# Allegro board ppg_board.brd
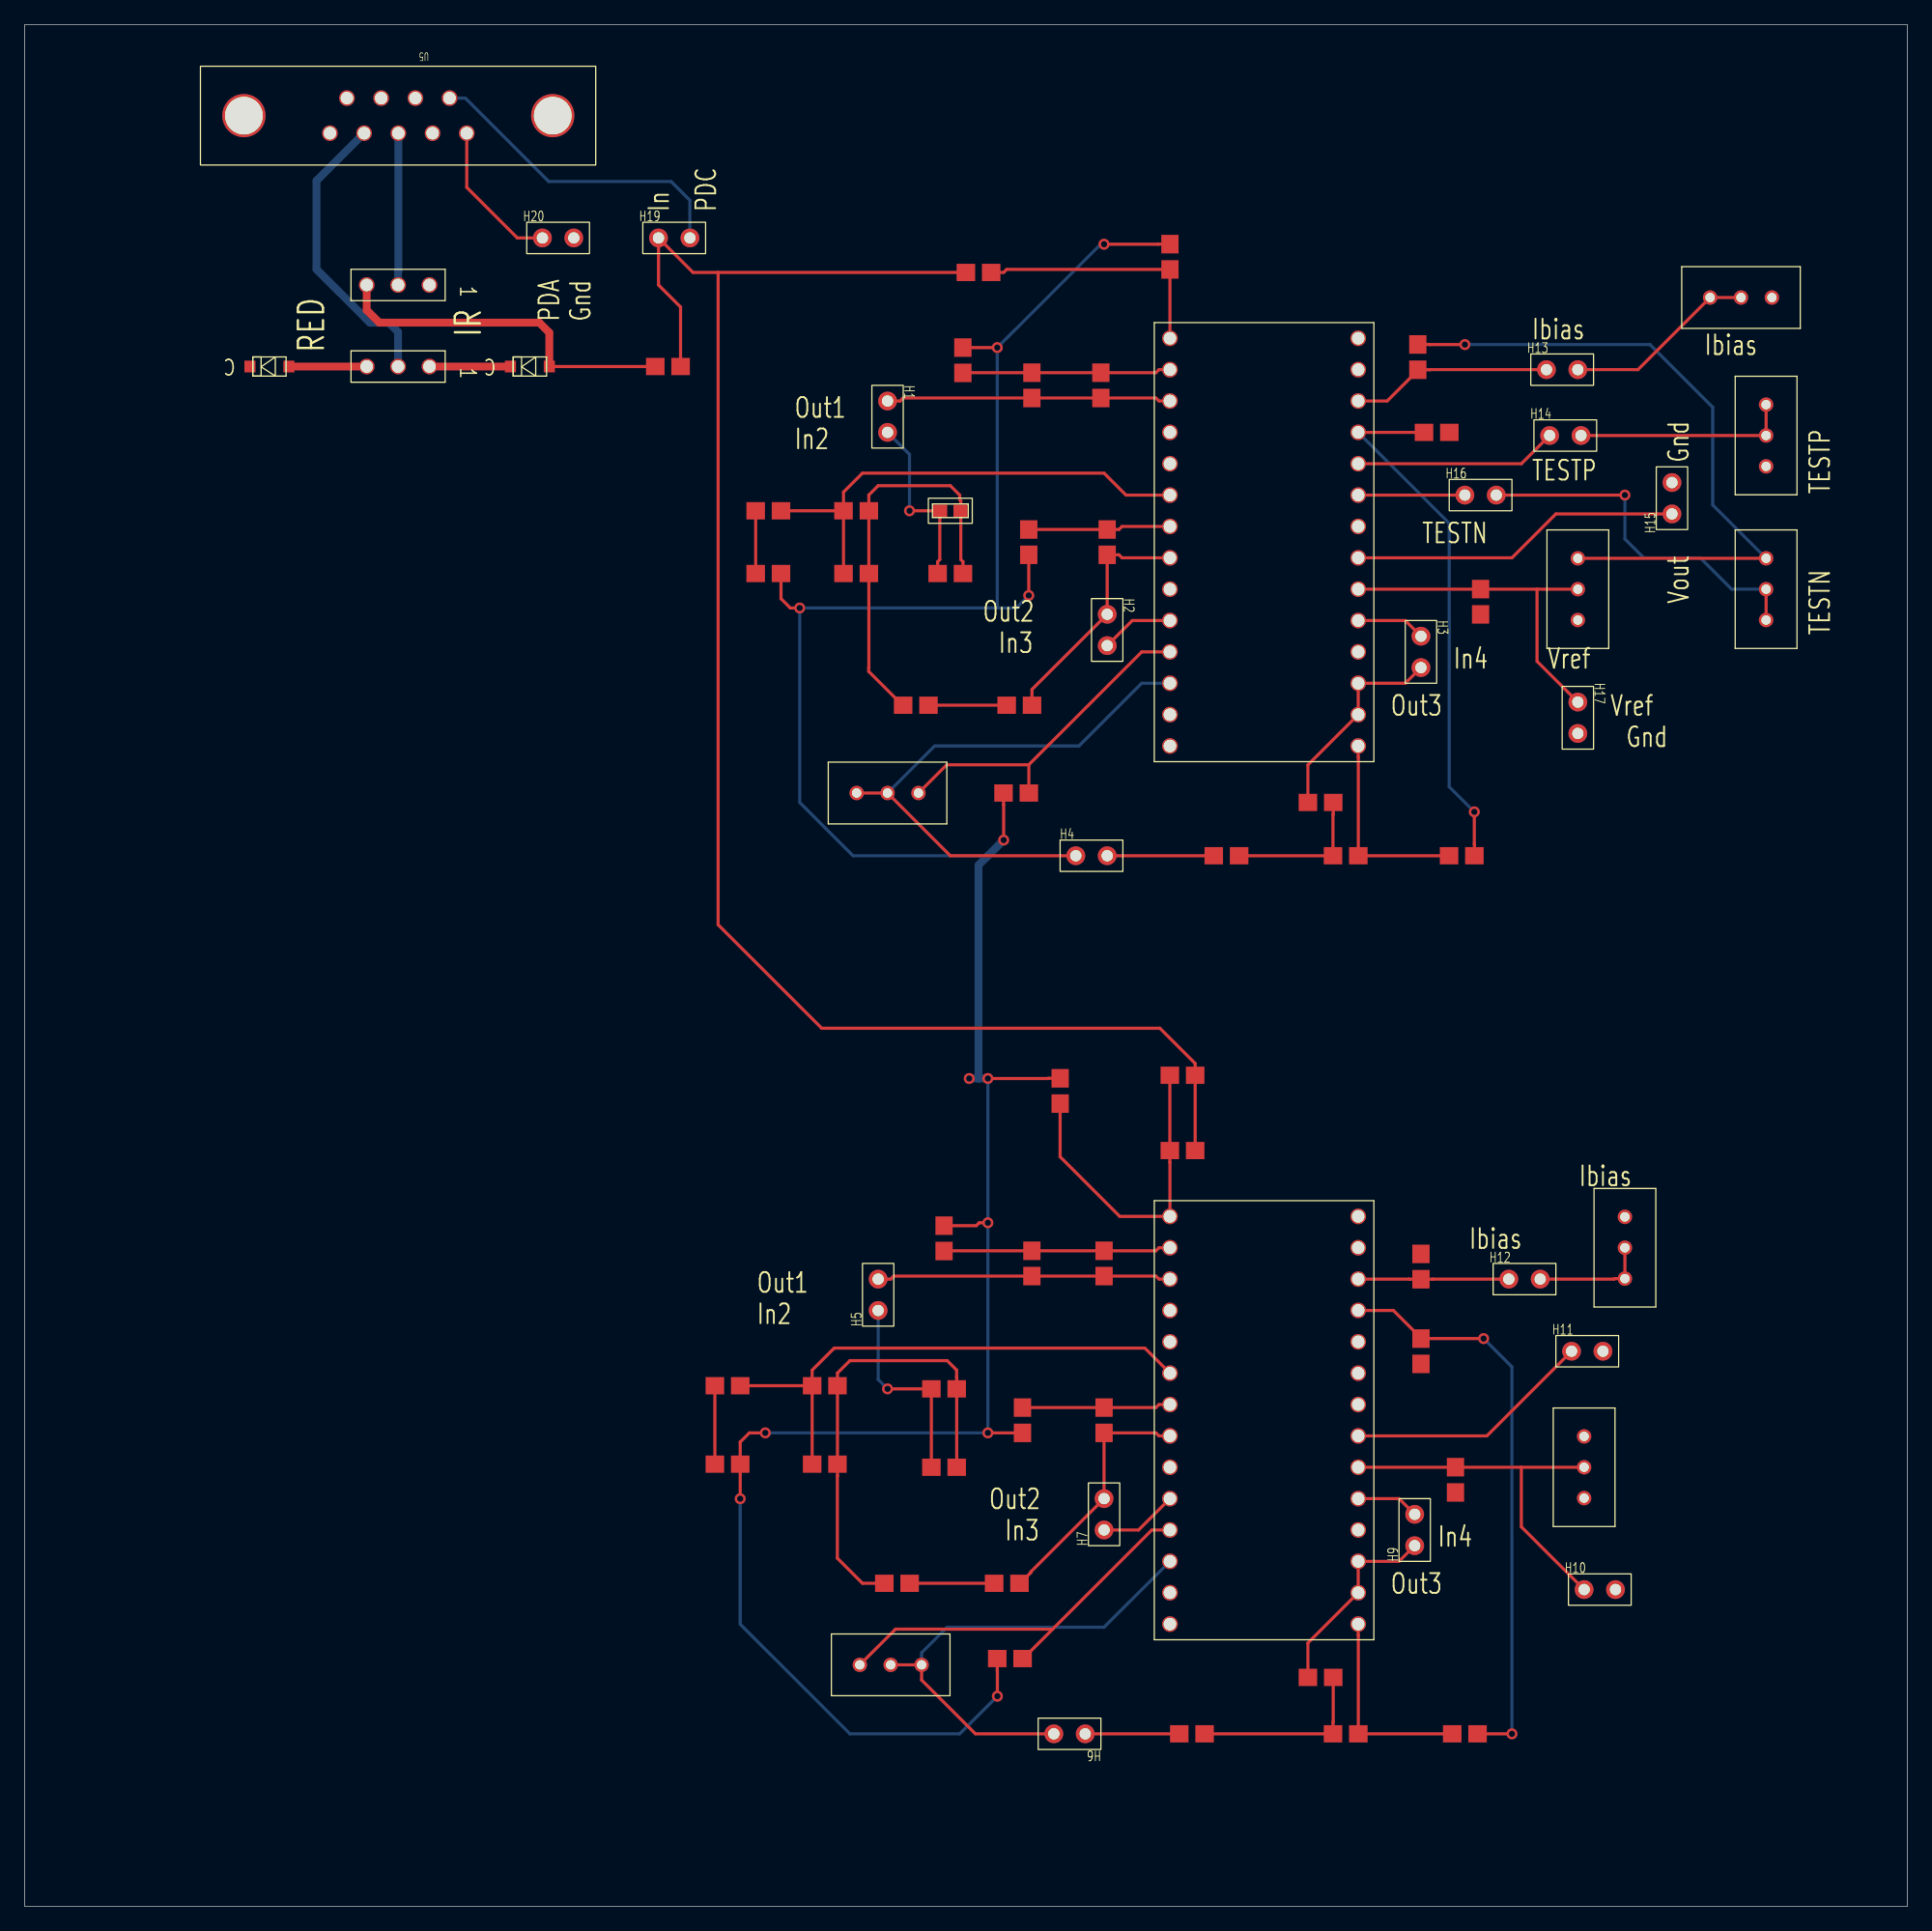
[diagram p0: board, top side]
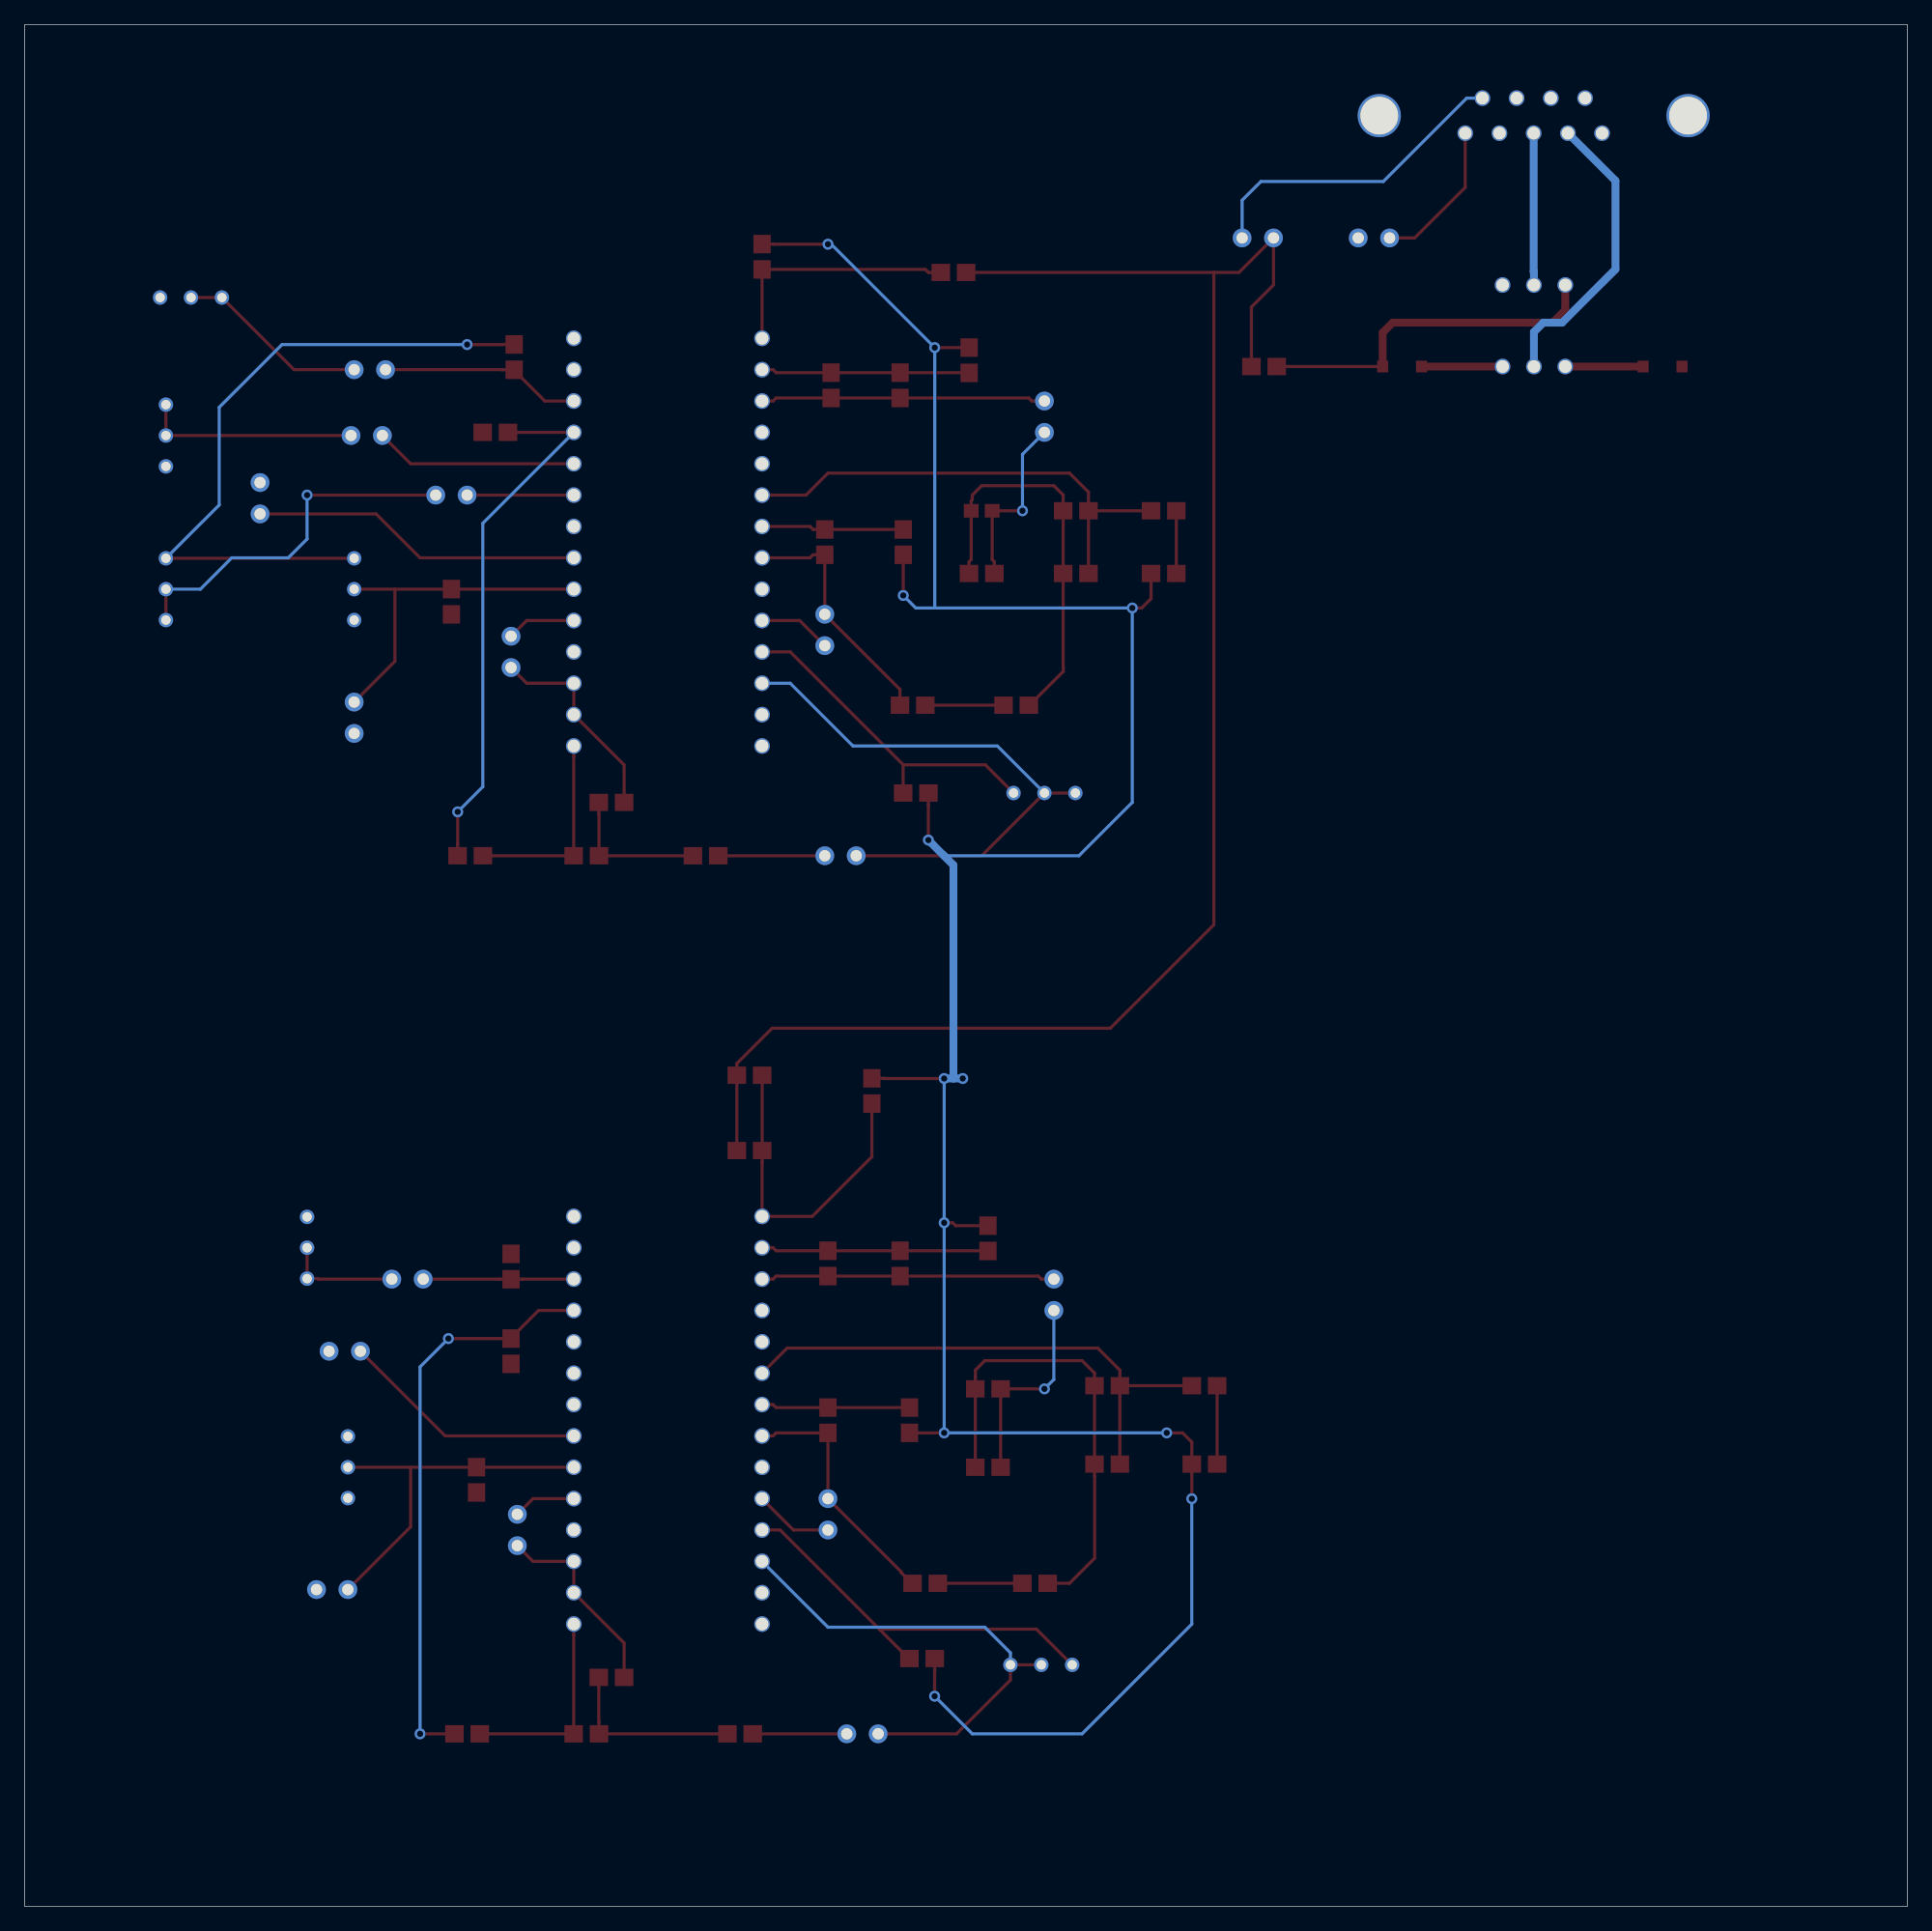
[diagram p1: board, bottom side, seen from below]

Outline 152.4 x 152.4 mm; copper layers: TOP, BOTTOM. Coordinates in mm from the lower left corner of the outline.
Outline path: 0,152.4 0,0 152.4,0 152.4,152.4 0,152.4

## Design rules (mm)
net group PB: nets PB<0> PB<1> PB<2> PB<3> PB<4> PB<5>
net group PD: nets PD<0> PD<1> PD<2> PD<3> PD<4> PD<5> PD<6> PD<7>

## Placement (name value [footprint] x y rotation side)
C1  -  [GR_0805]  77.22 132.33 0 top
C2  -  [GR_0805]  87.12 123.19 270 top
C3  -  [GR_0603]  74.93 113.03 0 top
C4  -  [GR_0805]  74.93 107.95 0 top
C5  -  [GR_0805]  67.31 113.03 180 top
C6  -  [GR_0805]  67.31 107.95 180 top
C7  -  [GR_0805]  93.73 61.21 0 top
C8  -  [GR_0805]  93.73 67.31 0 top
C9  -  [GR_0805]  87.38 52.07 90 top
C10  -  [GR_0805]  74.42 41.91 180 top
C11  -  [GR_0805]  74.42 35.56 180 top
C12  -  [GR_0805]  64.77 42.16 0 top
C13  -  [GR_0805]  64.77 35.81 0 top
C14  -  [GR_0805]  116.59 13.97 180 top
C15  -  [GR_0805]  115.82 34.54 90 top
C16  -  [GR_0805]  113.03 44.96 90 top
C17  -  [GR_0805]  113.03 51.82 270 top
C18  -  [GR_0805]  112.78 125.48 270 top
C19  -  [GR_0805]  114.3 119.38 180 top
C20  -  [GR_0805]  104.9 18.54 180 top
C21  -  [GR_0805]  116.33 85.09 180 top
C22  -  [GR_0805]  104.9 89.41 0 top
C23  -  [GR_0805]  117.86 105.66 90 top
H1  -  [JUMPER2]  69.85 121.92 270 top
H2  -  [JUMPER2]  87.63 104.65 270 top
H3  -  [JUMPER2]  113.03 102.87 270 top
H4  -  [JUMPER2]  85.09 85.09 0 top
H5  -  [JUMPER2]  69.09 48.26 90 top
H6  -  [JUMPER2]  85.85 13.97 180 top
H7  -  [JUMPER2]  87.38 30.48 90 top
H8  -  [GR_HEADER_SIP3]  30.23 131.32 270 top
H9  -  [JUMPER2]  112.52 29.21 90 top
H10  -  [JUMPER2]  126.24 25.65 0 top
H11  -  [JUMPER2]  125.22 44.96 0 top
H12  -  [JUMPER2]  120.14 50.8 0 top
H13  -  [JUMPER2]  123.19 124.46 0 top
H14  -  [JUMPER2]  123.44 119.13 0 top
H15  -  [JUMPER2]  133.35 112.78 90 top
H16  -  [JUMPER2]  116.59 114.3 0 top
H17  -  [JUMPER2]  125.73 97.54 270 top
H18  -  [GR_HEADER_SIP3]  30.23 124.71 270 top
H19  -  [JUMPER2]  51.31 135.13 0 top
H20  -  [JUMPER2]  41.91 135.13 0 top
R2  -  [GR_0805]  87.38 39.37 90 top
R3  -  [GR_0805]  79.5 26.16 180 top
R4  -  [GR_0805]  80.77 39.37 270 top
R5  -  [MURATAPV36W]  138.94 130.3 90 top
R6  -  [MURATAPV36W]  126.24 35.56 0 top
R7  -  [MURATAPV36W]  140.97 119.13 0 top
R8  -  [MURATAPV36W]  129.54 53.34 180 top
R9  -  [GR_0805]  56.9 35.81 0 top
R10  -  [GR_0805]  56.9 42.16 180 top
R11  -  [GR_0805]  70.61 26.16 180 top
R12  -  [MURATAPV36W]  140.97 106.68 180 top
R13  -  [GR_0805]  81.53 52.07 90 top
R14  -  [GR_0805]  52.07 124.71 180 top
R15  -  [GR_0805]  74.42 54.1 90 top
R16  -  [GR_0805]  83.82 66.04 90 top
R17  -  [MURATAPV36W]  125.73 106.68 0 top
R18  -  [GR_0805]  94.49 13.97 0 top
R19  -  [MURATAPV36W]  69.85 90.17 270 top
R20  -  [GR_0805]  106.93 13.97 0 top
R21  -  [MURATAPV36W]  70.1 19.56 270 top
R22  -  [GR_0805]  92.71 133.6 90 top
R23  -  [GR_0805]  75.95 125.22 90 top
R24  -  [GR_0805]  81.53 123.19 270 top
R25  -  [GR_0805]  72.14 97.28 0 top
R26  -  [GR_0805]  60.2 107.95 0 top
R27  -  [GR_0805]  60.2 113.03 180 top
R28  -  [GR_0805]  81.28 110.49 270 top
R29  -  [GR_0805]  80.52 97.28 0 top
R30  -  [GR_0805]  87.63 110.49 270 top
R31  -  [GR_0805]  79.76 20.07 180 top
R32  -  [GR_0805]  80.26 90.17 180 top
R33  -  [GR_0805]  106.93 85.09 180 top
R34  -  [GR_0805]  97.28 85.09 180 top
U1  -  [DIP28_SOCKET]  100.33 110.49 0 top
U2  -  [DIP28_SOCKET]  100.33 39.37 0 top
U3  -  [GR_SOD123]  19.81 124.71 180 top
U4  -  [GR_SOD123]  40.89 124.71 180 top
U5  -  [GR_DB9_AE10924-ND]  30.23 145.03 180 top

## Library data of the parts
C1 = GR_CAP: part number: GR_CAP-1.2UF,GR_0805,10%
C2 C13 = GR_CAP: part number: GR_CAP-150NF,GR_0805,10%
C3 = GR_CAP: part number: GR_CAP-15UF,GR_0603,20%
C4 = GR_CAP: part number: GR_CAP-1UF,GR_0805,10%
C5 = GR_CAP: part number: GR_CAP-4.7UF,GR_0805,10%
C6 C10 = GR_CAP: part number: GR_CAP-1.5UF,GR_0805,10%
C7 = GR_CAP: part number: GR_CAP-120NF,GR_0805,5%
C8 C12 = GR_CAP: part number: GR_CAP-470NF,GR_0805,10%
C9 C11 C14 C20-C22 = GR_CAP: part number: GR_CAP-100NF,GR_0805,10%
C15-C19 C23 = GR_CAP: part number: GR_CAP-10NF,GR_0805,10%
H1-H7 H9-H17 H19 H20 = HEADER_SIP2: part number: HEADER_SIP2-SIP HEADER
H8 H18 = GR_HEADER_SIP3
R2 R30 = GR_RES: part number: GR_RES-40.2K,1%,GR_0805
R3 R10 = GR_RES: part number: GR_RES-619K,1%,GR_0805
R4 R28 R32 = GR_RES: part number: GR_RES-10K,1%,GR_0805
R5 R7 R8 R12 = POT: part number: POT-500K,MURATAPV36W
R6 R17 = POT: part number: POT-200K,MURATAPV36W
R9 R26 = GR_RES: part number: GR_RES-0,JUMPER,GR_0805
R11 = GR_RES: part number: GR_RES-976K,1%,GR_0805
R13 R16 = GR_RES: part number: GR_RES-499K,1%,GR_0805
R14 R15 = GR_RES: part number: GR_RES-100K,1%,GR_0805
R18 R20 = GR_RES: part number: GR_RES-110K,1%,GR_0805
R19 R21 = POT: part number: POT-100K,MURATAPV36W
R22 = GR_RES: part number: GR_RES-3.01M,1%,GR_0805
R23 R33 R34 = GR_RES: part number: GR_RES-1.00M,1%,GR_0805
R24 = GR_RES: part number: GR_RES-4.99M,1%,GR_0805
R25 = GR_RES: part number: GR_RES-9.76M,1%,GR_0805
R27 R29 = GR_RES: part number: GR_RES-6.19M,1%,GR_0805
R31 = GR_RES: part number: GR_RES-49.9K,1%,GR_0805
U1 U2 = DIP28_SOCKET
U3 U4 = GR_AL5809
U5 = GR_NELLCOR_DB9

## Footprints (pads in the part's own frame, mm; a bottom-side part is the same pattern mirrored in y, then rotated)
DIP28_SOCKET
  round 1.27 hole 1.016: 1(-7.62,16.51) 2(-7.62,13.97) 3(-7.62,11.43) 4(-7.62,8.89) 5(-7.62,6.35) 6(-7.62,3.81) 7(-7.62,1.27) 8(-7.62,-1.27) 9(-7.62,-3.81) 10(-7.62,-6.35) 11(-7.62,-8.89) 12(-7.62,-11.43) 13(-7.62,-13.97) 14(-7.62,-16.51) 15(7.62,-16.51) 16(7.62,-13.97) 17(7.62,-11.43) 18(7.62,-8.89) 19(7.62,-6.35) 20(7.62,-3.81) 21(7.62,-1.27) 22(7.62,1.27) 23(7.62,3.81) 24(7.62,6.35) 25(7.62,8.89) 26(7.62,11.43) 27(7.62,13.97) 28(7.62,16.51)
GR_0603
  rect 1.2x1.1 smd: 1(-0.85,0) 2(0.85,0)
GR_0805
  rect 1.5x1.4 smd: 1(-1.025,0) 2(1.025,0)
GR_DB9_AE10924-ND
  round 3.5 hole 3.05: (-12.52,0) (12.48,0)
  round 1.27 hole 1.016: 1(5.52,1.42) 2(2.75,1.42) 3(-0.02,1.42) 4(-2.79,1.42) 5(-5.56,1.42) 6(4.14,-1.42) 7(1.37,-1.42) 8(-1.4,-1.42) 9(-4.17,-1.42)
GR_HEADER_SIP3
  round 1.27 hole 1.016: 1(0,2.54) 2(0,0) 3(0,-2.54)
GR_SOD123
  rect 0.9x0.95 smd: 1(-1.575,0) 2(1.575,0)
JUMPER2
  round 1.524 hole 0.914: 1(0,0) 2(2.54,0)
MURATAPV36W
  round 1.168 hole 0.762: 1(0,2.5) 2(0,0) 3(0,-2.5)

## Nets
GND: C15.1 C16.1 C19.1 C23.1 H8.1 H10.2 H11.2 H15.2 H17.2 H20.2 R5.3 R6.3 R7.3 R8.3 R17.3 U1.13 U1.14 U2.13 U2.14 U3.2(CATHODE)
VDD_5: H8.3 R14.2 U4.1(ANODE)
VDD_18: C17.1 C18.1 R6.1 R12.3 R17.1
VDDA: U1.27 U1.28 U2.27 U2.28
UNNAMED_1_DIP28SOCKET_I8_IBIAS: C18.2 H13.1 U1.26(IBIAS)
UNNAMED_1_DIP28SOCKET_I8_OUT2: H2.1 R29.2 R30.2 U1.8(OUT2)
UNNAMED_1_DIP28SOCKET_I8_OUT3: H4.1 R19.2 R19.3 U1.12(OUT3)
UNNAMED_1_DIP28SOCKET_I8_TESTN: H16.1 U1.23(TESTN)
UNNAMED_1_DIP28SOCKET_I8_TESTP: H14.1 U1.24(TESTP)
UNNAMED_1_DIP28SOCKET_I8_VIN1: C1.2 R22.1 U1.1(VIN1+)
UNNAMED_1_DIP28SOCKET_I8_VIN1_1: C2.1 R23.1 R24.1 U1.2(VIN1-)
UNNAMED_1_DIP28SOCKET_I8_VIN2: R28.1 R30.1 U1.7(VIN2-)
UNNAMED_1_DIP28SOCKET_I8_VIN2_1: C5.2 C6.2 R27.1 U1.6(VIN2+)
UNNAMED_1_DIP28SOCKET_I8_VIN3: R19.1 R32.1 U1.11(VIN3-)
UNNAMED_1_DIP28SOCKET_I8_VIN3_1: H2.2 U1.10(VIN3+)
UNNAMED_1_DIP28SOCKET_I8_VIN4: C21.2 R33.1 U1.15(VIN4+)
UNNAMED_1_DIP28SOCKET_I8_VIN4_1: C22.1 H3.2 U1.16(VIN4-) U1.17(VOUT4)
UNNAMED_1_DIP28SOCKET_I8_VINCOM: H3.1 U1.19(VIN_COMP)
UNNAMED_1_DIP28SOCKET_I8_VOUT1: C2.2 H1.1 R24.2 U1.3(VOUT1)
UNNAMED_1_DIP28SOCKET_I8_VOUTCO: H15.1 U1.21(VOUT_COMP)
UNNAMED_1_DIP28SOCKET_I8_VREFCO: C23.2 H17.1 R17.2 U1.20(VREF_COMP)
UNNAMED_1_DIP28SOCKET_I53_IBIAS: C17.2 H12.1 U2.26(IBIAS)
UNNAMED_1_DIP28SOCKET_I53_OUT2: H7.2 R2.1 R3.1 U2.8(OUT2)
UNNAMED_1_DIP28SOCKET_I53_OUT3: H6.2 R21.1 R21.2 U2.12(OUT3)
UNNAMED_1_DIP28SOCKET_I53_VIN1: C7.1 C8.1 R16.1 U2.1(VIN1+)
UNNAMED_1_DIP28SOCKET_I53_VIN1_: C9.2 R13.2 R15.1 U2.2(VIN1-)
UNNAMED_1_DIP28SOCKET_I53_VIN2: C12.1 C13.1 R10.1 U2.6(VIN2+)
UNNAMED_1_DIP28SOCKET_I53_VIN2_: R2.2 R4.1 U2.7(VIN2-)
UNNAMED_1_DIP28SOCKET_I53_VIN3: H7.1 U2.10(VIN3+)
UNNAMED_1_DIP28SOCKET_I53_VIN3_: R21.3 R31.1 U2.11(VIN3-)
UNNAMED_1_DIP28SOCKET_I53_VIN4: C20.2 H9.1 U2.16(VIN4-) U2.17(VOUT4)
UNNAMED_1_DIP28SOCKET_I53_VIN4_: C14.2 R20.2 U2.15(VIN4+)
UNNAMED_1_DIP28SOCKET_I53_VINCO: H9.2 U2.19(VIN_COMP)
UNNAMED_1_DIP28SOCKET_I53_VOUT1: C9.1 H5.2 R13.1 U2.3(VOUT1)
UNNAMED_1_DIP28SOCKET_I53_VOUTC: H11.1 U2.21(VOUT_COMP)
UNNAMED_1_DIP28SOCKET_I53_VREFC: C15.2 H10.1 R6.2 U2.20(VREF_COMP)
UNNAMED_1_GRAL5809_I76_CATHODE: H18.1 U4.2(CATHODE)
UNNAMED_1_GRAL5809_I77_ANODE: H18.3 U3.1(ANODE)
UNNAMED_1_GRCAP_IC3RR_1: C3.1 C4.1 H1.2
UNNAMED_1_GRCAP_IC3RR_2: C3.2 C4.2 C5.1 C6.1 R25.1
UNNAMED_1_GRCAP_IC4HR_1: C10.1 C11.1 C12.2 C13.2 R11.2
UNNAMED_1_GRCAP_IC4HR_2: C10.2 C11.2 H5.1
UNNAMED_1_GRCAP_IC7RR_2: C22.2 R33.2 R34.1
UNNAMED_1_GRCAP_IC9HR_1: C20.1 R18.2 R20.1
UNNAMED_1_GRHEADERSIP3_I74_2: H8.2 U5.3(IR_CATHODE)
UNNAMED_1_GRHEADERSIP3_I75_2: H18.2 U5.2(IR_ANODE)
UNNAMED_1_GRNELLCORDB9_I71_PDAN: H20.1 U5.5(PD_ANODE)
UNNAMED_1_GRNELLCORDB9_I71_PDCA: H19.2 U5.9(PD_CATHODE)
UNNAMED_1_GRRES_IR4HR_2: R9.1 R10.2
UNNAMED_1_GRRES_IR4RR_2: R26.1 R27.2
UNNAMED_1_GRRES_IR6RR_2: R25.2 R29.1
UNNAMED_1_GRRES_IR7HR_2: R3.2 R11.1
UNNAMED_1_GRRES_IR12HR_1: H6.1 R18.1
UNNAMED_1_HEADERSIP2_I40_2: H4.2 R34.2
UNNAMED_1_HEADERSIP2_I66_2: H12.2 R8.1 R8.2
UNNAMED_1_POT_I4_2: H13.2 R5.1 R5.2
UNNAMED_1_POT_I45_1: H16.2 R12.1 R12.2
UNNAMED_1_POT_I46_1: H14.2 R7.1 R7.2
VCM: C14.1 C16.2 C19.2 C21.1 R4.2 R9.2 R15.2 R16.2 R22.2 R23.2 R26.2 R28.2 R31.2 R32.2 U1.25(VCMA) U2.25(VCMA)
VOUT_PD: C1.1 C7.2 C8.2 H19.1 R14.1

Pads without a net: U1 4 5 9 18 22; U2 4 5 9 18 22 23 24; U5 1 4 6 7 8

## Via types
v1: diameter 0.889, hole 0.508, TOP to BOTTOM, 19 vias

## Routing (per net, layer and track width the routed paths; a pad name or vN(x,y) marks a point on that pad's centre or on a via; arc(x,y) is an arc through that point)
VDD_5: length 28.9
  TOP w0.254: U4.1 R14.2
  TOP w0.635: U4.1 42.47,127.46 41.66,128.27 28.7,128.27 27.69,129.29 H8.3
VDD_18: length 55.2
  TOP w0.254: R17.1 R12.3 ; C18.1 113.73,126.5 113.74,126.49 v1(116.59,126.49)
  BOTTOM w0.254: v1(116.59,126.49) 131.57,126.49 136.65,121.41 136.65,113.5 R12.3
UNNAMED_1_DIP28SOCKET_I8_IBIAS: length 16.3
  TOP w0.254: U1.26 110.29,121.92 112.78,124.4 C18.2 113.73,124.45 113.74,124.46 H13.1
UNNAMED_1_DIP28SOCKET_I8_OUT2: length 19.9
  TOP w0.254: R29.2 81.54,98.56 H2.1 R30.2 88.58,109.47 88.83,109.22 U1.8
UNNAMED_1_DIP28SOCKET_I8_OUT3: length 46.4
  TOP w0.254: R19.3 R19.2 74.93,85.09 H4.1
  BOTTOM w0.254: R19.2 73.66,93.98 85.34,93.98 90.42,99.06 U1.12
UNNAMED_1_DIP28SOCKET_I8_TESTN: length 8.6
  TOP w0.254: H16.1 U1.23
UNNAMED_1_DIP28SOCKET_I8_TESTP: length 16.4
  TOP w0.254: H14.1 121.16,116.84 U1.24
UNNAMED_1_DIP28SOCKET_I8_VIN1: length 20.1
  TOP w0.254: U1.1 R22.1 79.49,132.58 79.24,132.33 C1.2
UNNAMED_1_DIP28SOCKET_I8_VIN1_1: length 16.9
  TOP w0.254: 75.95,124.21 R24.1 C2.1 91.58,124.21 91.82,124.46 U1.2
UNNAMED_1_DIP28SOCKET_I8_VIN2: length 11.5
  TOP w0.254: R28.1 R30.1 88.58,111.51 88.83,111.76 U1.7
UNNAMED_1_DIP28SOCKET_I8_VIN2_1: length 39.5
  TOP w0.254: R27.1 C5.2 ; C5.2 C6.2 ; C5.2 66.29,114.55 67.82,116.08 87.38,116.08 89.15,114.3 U1.6
UNNAMED_1_DIP28SOCKET_I8_VIN3: length 27.4
  TOP w0.254: R19.1 74.64,92.46 81.28,92.46 ; U1.11 90.42,101.6 81.29,92.46 R32.1
UNNAMED_1_DIP28SOCKET_I8_VIN3_1: length 5.9
  TOP w0.254: H2.2 89.66,104.14 U1.10
UNNAMED_1_DIP28SOCKET_I8_VIN4: length 16.2
  TOP w0.254: U1.15 107.95,93.09 107.96,93.08 R33.1 C21.2
UNNAMED_1_DIP28SOCKET_I8_VIN4_1: length 16.9
  TOP w0.254: C22.1 103.88,92.45 U1.16 U1.17 111.76,99.06 H3.2
UNNAMED_1_DIP28SOCKET_I8_VINCOM: length 5.6
  TOP w0.254: U1.19 111.76,104.14 H3.1
UNNAMED_1_DIP28SOCKET_I8_VOUT1: length 23.1
  TOP w0.254: H1.1 70.87,121.92 71.11,122.17 R24.2 C2.2 91.58,122.17 91.82,121.92 U1.3
UNNAMED_1_DIP28SOCKET_I8_VOUTCO: length 26.9
  TOP w0.254: U1.21 120.4,109.22 123.95,112.78 H15.1
UNNAMED_1_DIP28SOCKET_I8_VREFCO: length 28.3
  TOP w0.254: U1.20 122.43,106.68 ; 122.43,106.68 122.43,100.84 H17.1 ; 122.43,106.68 R17.2
UNNAMED_1_DIP28SOCKET_I53_IBIAS: length 12.2
  TOP w0.254: H12.1 113.99,50.8 113.98,50.79 C17.2 112.08,50.79 112.07,50.8 U2.26
UNNAMED_1_DIP28SOCKET_I53_OUT2: length 20.5
  TOP w0.254: U2.8 91.82,38.1 91.58,38.35 R2.1 H7.2 81.46,27.1 81.46,27.04 80.58,26.16 R3.1
UNNAMED_1_DIP28SOCKET_I53_OUT3: length 40.4
  TOP w0.254: H6.2 76.96,13.97 72.6,18.33 R21.1 R21.2
  BOTTOM w0.254: U2.12 87.38,22.61 74.68,22.61 72.6,20.53 R21.1
UNNAMED_1_DIP28SOCKET_I53_VIN1: length 26.6
  TOP w0.254: R16.1 83.82,60.71 88.65,55.88 U2.1 92.71,60.25 92.7,60.26 C7.1 C8.1
UNNAMED_1_DIP28SOCKET_I53_VIN1_: length 17.9
  TOP w0.254: 74.93,53.09 R13.2 C9.2 91.58,53.09 91.82,53.34 U2.2
UNNAMED_1_DIP28SOCKET_I53_VIN2: length 44
  TOP w0.254: R10.1 C12.1 ; C12.1 63.75,43.43 65.53,45.21 90.68,45.21 U2.6 ; C12.1 C13.1
UNNAMED_1_DIP28SOCKET_I53_VIN2_: length 12
  TOP w0.254: R4.1 R2.2 91.58,40.39 91.82,40.64 U2.7
UNNAMED_1_DIP28SOCKET_I53_VIN3: length 6.4
  TOP w0.254: U2.10 90.17,30.48 H7.1
UNNAMED_1_DIP28SOCKET_I53_VIN3_: length 33.1
  TOP w0.254: R21.3 70.5,22.45 83.21,22.45 ; U2.11 91.24,30.48 83.21,22.45 ; 83.21,22.45 80.83,20.07 R31.1
UNNAMED_1_DIP28SOCKET_I53_VIN4: length 16.2
  TOP w0.254: C20.2 103.88,21.33 U2.16 U2.17 111.25,27.94 H9.1
UNNAMED_1_DIP28SOCKET_I53_VIN4_: length 16.5
  TOP w0.254: U2.15 107.95,21.97 107.96,21.96 R20.2 C14.2
UNNAMED_1_DIP28SOCKET_I53_VINCO: length 5.1
  TOP w0.254: H9.2 111.25,33.02 U2.19
UNNAMED_1_DIP28SOCKET_I53_VOUT1: length 23.8
  TOP w0.254: U2.3 91.82,50.8 91.58,51.05 C9.1 R13.1 70.35,51.05 70.1,50.8 H5.2
UNNAMED_1_DIP28SOCKET_I53_VOUTC: length 20.1
  TOP w0.254: H11.1 118.36,38.1 U2.21
UNNAMED_1_DIP28SOCKET_I53_VREFC: length 30.3
  TOP w0.254: 121.16,35.56 R6.2 ; 121.16,35.56 121.16,30.73 H10.1 ; 121.16,35.56 U2.20
UNNAMED_1_GRAL5809_I76_CATHODE: length 6.6
  TOP w0.635: U4.2 H18.1
UNNAMED_1_GRAL5809_I77_ANODE: length 6.3
  TOP w0.635: U3.1 H18.3
UNNAMED_1_GRCAP_IC3RR_1: length 14.7
  TOP w0.254: v1(71.63,113.03) C3.1 74.08,109.08 73.91,108.9 C4.1
  BOTTOM w0.254: H1.2 71.63,117.6 v1(71.63,113.03)
UNNAMED_1_GRCAP_IC3RR_2: length 32.7
  TOP w0.254: R25.1 71.06,97.28 68.33,100.02 68.33,100.33 68.33,100.34 C6.1 C5.1 68.33,114.31 69.09,115.06 74.93,115.06 75.69,114.3 75.69,113.92 75.78,113.83 C3.2 75.78,109.08 75.95,108.9 C4.2
UNNAMED_1_GRCAP_IC4HR_1: length 37.9
  TOP w0.254: R11.2 67.82,26.16 65.79,28.19 65.79,34.85 65.79,34.86 C13.2 C12.2 65.79,43.19 66.8,44.2 74.68,44.2 75.44,43.43 75.44,42.87 75.45,42.86 C10.1 C11.1
UNNAMED_1_GRCAP_IC4HR_2: length 16.6
  TOP w0.254: C11.2 C10.2 v1(69.85,41.91)
  BOTTOM w0.254: H5.1 69.09,42.67 v1(69.85,41.91)
UNNAMED_1_GRCAP_IC7RR_2: length 11.9
  TOP w0.254: C22.2 105.93,88.45 105.91,88.44 R33.2 R34.1
UNNAMED_1_GRCAP_IC9HR_1: length 15
  TOP w0.254: C20.1 105.93,14.94 105.91,14.92 R20.1 R18.2
UNNAMED_1_GRHEADERSIP3_I74_2: length 12.3
  BOTTOM w0.635: H8.2 30.23,132.4 30.25,132.42 U5.3
UNNAMED_1_GRHEADERSIP3_I75_2: length 24.1
  BOTTOM w0.635: U5.2 23.62,139.76 23.62,132.59 27.94,128.27 29.46,128.27 30.23,127.51 H18.2
UNNAMED_1_GRNELLCORDB9_I71_PDAN: length 12.2
  TOP w0.254: H20.1 39.88,135.13 35.79,139.22 U5.5
UNNAMED_1_GRNELLCORDB9_I71_PDCA: length 25.9
  BOTTOM w0.254: U5.9 35.66,146.45 42.42,139.7 52.32,139.7 53.85,138.18 H19.2
UNNAMED_1_GRRES_IR4HR_2: length 6.3
  TOP w0.254: R9.1 R10.2
UNNAMED_1_GRRES_IR4RR_2: length 5.1
  TOP w0.254: R27.2 R26.1
UNNAMED_1_GRRES_IR6RR_2: length 6.3
  TOP w0.254: R29.1 R25.2
UNNAMED_1_GRRES_IR7HR_2: length 6.8
  TOP w0.254: R3.2 R11.1
UNNAMED_1_GRRES_IR12HR_1: length 7.6
  TOP w0.254: R18.1 H6.1
UNNAMED_1_HEADERSIP2_I40_2: length 8.6
  TOP w0.254: H4.2 R34.2
UNNAMED_1_HEADERSIP2_I66_2: length 9.4
  TOP w0.254: H12.2 128.66,50.8 128.7,50.84 R8.1 R8.2
UNNAMED_1_POT_I4_2: length 15.6
  TOP w0.254: R5.2 R5.1 130.6,124.46 H13.2
UNNAMED_1_POT_I45_1: length 29.6
  TOP w0.254: R12.1 R12.2 ; H16.2 v1(129.54,114.3)
  BOTTOM w0.254: v1(129.54,114.3) 129.54,110.74 131.06,109.22 135.64,109.22 138.18,106.68 R12.2
UNNAMED_1_POT_I46_1: length 17.5
  TOP w0.254: H14.2 R7.2 R7.1
VCM: length 321
  TOP w0.254: U2.25 110.8,48.26 113.03,46.03 C16.2 v1(118.1,45.98) ; v1(59.95,38.35) 58.67,38.35 57.92,37.6 R9.2 v1(57.92,33.01) ; v1(120.4,13.97) C14.1 ; v1(62.74,105.16) 61.98,105.16 61.22,105.91 R26.2 ; v1(77.97,55.36) 77.27,55.36 77.03,55.13 R15.2 ; C21.1 117.36,86.04 117.35,86.05 v1(117.35,88.65) ; v1(79.25,86.36) 79.25,89.21 79.24,89.22 R32.2 ; v1(87.38,134.62) 91.75,134.62 91.76,134.63 R22.2 ; v1(78.74,17.02) 78.74,19.1 78.73,19.11 R31.2 ; R28.2 v1(81.28,106.17) ; U1.25 C19.2 ; R23.2 v1(78.73,126.25) ; R16.2 82.87,67.06 82.85,67.05 v1(77.97,67.05) ; R4.2 v1(77.97,38.35)
  BOTTOM w0.254: v1(81.28,106.17) 80.26,105.16 78.74,105.16 ; 78.74,105.16 v1(62.74,105.16) 62.74,89.41 67.06,85.09 77.98,85.09 ; 78.74,105.16 78.73,105.16 v1(78.73,126.25) 87.1,134.62 v1(87.38,134.62) ; v1(120.4,13.97) 120.4,43.69 v1(118.1,45.98) ; v1(77.97,67.05) v1(77.97,55.36) v1(77.97,38.35) v1(59.95,38.35) ; v1(78.74,17.02) 75.69,13.97 66.8,13.97 57.92,22.85 v1(57.92,33.01) ; U1.25 115.32,112.01 115.32,90.68 v1(117.35,88.65)
  BOTTOM w0.635: v1(79.25,86.36) 77.22,84.33 77.22,67.05 ; v1(77.97,67.05) 77.22,67.05 ; 77.22,67.05 v1(76.46,67.05)
VOUT_PD: length 140.3
  TOP w0.254: C7.2 C8.2 94.75,68.26 91.89,71.12 64.52,71.12 56.13,79.5 56.13,132.33 ; C1.1 56.13,132.33 ; 56.13,132.33 54.1,132.33 H19.1 51.31,131.32 53.09,129.53 R14.1

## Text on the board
Ref Des/Silkscreen Top: Out1 | In2 | Out2 | In3 | Out3 | TESTN | In4 | Ibias | TESTP | Vref | Gnd | PDA | In | PDC | Vout | RED | IR
